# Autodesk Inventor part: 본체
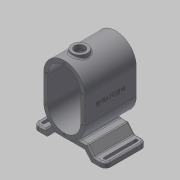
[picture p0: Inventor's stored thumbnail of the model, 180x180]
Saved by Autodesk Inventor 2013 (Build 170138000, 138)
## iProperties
Created: 2016-12
Part Number: 본체
Material: 알루미늄 6061
Document SubType Name: Modeling
Designer: mduedu
Density: 2.71 g/cm^3
Mass: 1017.21 g
Surface Area: 965.782 cm^2
Volume: 375.354 cm^3
Author: mduedu
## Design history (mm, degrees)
sketch "스케치1"
  geometry: L1 (40, -25)-(40, 25); L2 (-40, 25)-(-40, -25); L3 (-40, -25)-(40, 25); L4 (40, -25)-(-40, 25); L5 (0, 25)-(0, -25); A1 r 40 centre (0, 25) between (40, 25) and (-40, 25); A2 r 40 centre (0, -25) between (-40, -25) and (40, -25); 1 further point
  constraints: 10 end point, 4 point on circle, 3 tangent, 2 centre point, 2 midpoint, 2 parallel, 1 vertical
  dimensions: "d0" = 130 dimension on A2 A1; "d2" = 80 distance between parallel lines of L1 L2
extrude "돌출1" new body sketch "스케치1" stored distance "d3" = 100; taper "d4" = 0 deg
feature "쉘1" dims "d5" = 8
sketch "스케치15"
  geometry: L1 (-35, -64.5)-(35, -64.5); L2 (-35, -64.5)-(-47.586, -79.5); L3 (-47.586, -79.5)-(-70, -79.5); L4 (0, -64.5)-(0, 0); L5 (35, -64.5)-(47.586, -79.5); L6 (47.586, -79.5)-(70, -79.5); L7 (70, -89.5)-(42.923, -89.5); L8 (42.923, -89.5)-(30.337, -74.5); L9 (30.337, -74.5)-(-30.337, -74.5); L10 (-30.337, -74.5)-(-42.923, -89.5); L11 (-42.923, -89.5)-(-70, -89.5); L12 (-70, -79.5)-(-70, -89.5); L13 (70, -79.5)-(70, -89.5); A1 r 40 centre (0, -25) between (-40, -25) and (40, -25) reference; 1 further point
  constraints: 26 end point, 2 parallel, 2 perpendicular, 2 symmetric about line, 1 coincident, 1 horizontal, 1 midpoint, 1 vertical, 4 other
  dimensions: "d83" = 10 distance between parallel lines of L9 L1; "d85" = 140 distance between parallel lines of L13 L12; "d86" = 70 distance of L1.start L1.end; "d87" = 25 distance between parallel lines of L11 L1; "d88" = 130 deg angle of L1 L2; "d106" = 0.5 distance edge to line of A1 L1
extrude "돌출6" new body sketch "스케치15" stored distance "d89" = 80; taper "d90" = 0 deg
fillet "모깎기13" dims "d101" = 3
fillet "모깎기15" dims "d103" = 3
fillet "모깎기16" dims "d104" = 10
fillet "모깎기17" dims "d105" = 3
feature "결합2"
  node "솔리드2"
fillet "모깎기18" dims "d107" = 3
sketch "스케치16"
  geometry: L1 (8.015, 67)-(8.015, 7); L2 (14.015, 67)-(14.015, 7); A1 r 10 centre (11.015, 67) between (21.015, 67) and (11.015, 77) reference; A2 r 10 centre (11.015, 7) between (11.015, -3) and (21.015, 7) reference; A3 r 3 centre (11.015, 67) between (8.015, 67) and (14.015, 67); A4 r 3 centre (11.015, 7) between (8.015, 7) and (14.015, 7); 1 further point
  constraints: 4 end point, 4 point on circle, 4 tangent, 2 centre point, 2 coincident
  dimensions: "d108" = 6 diameter of A3; "d109" = 6 diameter of A4
extrude "돌출7" cut sketch "스케치16" stored distance "d110" = 80; taper "d111" = 0 deg
node "작업 평면1"
sketch "스케치9"
  geometry: 1 further point
sketch "스케치7"
  geometry: L1 (40, 50)-(-40, 50) reference; C1 r 15 at (0, 20); 1 further point
  constraints: 1 centre point, 1 vertical alignment
  dimensions: "d40" = 30 diameter of C1; "d41" = 30 distance from line of C1.centre L1
extrude "돌출4" join sketch "스케치7" stored distance "d42" = 80; taper "d43" = 0 deg
hole "구멍2" diameter "d46" = 20; stored, may be unused: countersink angle "d50" = 90 deg, drill point angle "d52" = 118 deg; dims "d44" = 10, "d45" = 10, "d47" = 6, "d48" = 4, "d49" = 2, "d51" = 8
fillet "모깎기4" dims "d53" = 3
node "작업 평면2"
sketch "스케치8"
  geometry: C1 r 15 at (0, 0) reference; C2 r 15 at (0, 0); 1 further point
  constraints: 1 centre point, 1 coincident
  dimensions: "d55" = 30 diameter of C2
extrude "돌출5" cut sketch "스케치8" stored distance "d56" = 80; taper "d57" = 0 deg
chamfer "모따기1" distance "d58" = 1; stored, may be unused: second distance "d59" = 2, angle "d60" = 45 deg
sketch "스케치10"
  geometry: 2 further points
  constraints: 1 coincident, 1 other
feature "엠보싱1" sketch "스케치10" dims "d0" = 130, "d2" = 80, "d61" = 0.5, "d62" = 0
sketch "스케치11"
  geometry: 1 further point
  constraints: 1 other
hole "구멍3" sketch "스케치11" at (0, 60) diameter "d63" = 3.242; stored, may be unused: countersink angle "d67" = 90 deg, drill point angle "d69" = 120 deg; dims "d64" = 8.6, "d65" = 4, "d66" = 2, "d68" = 10.6
sketch "스케치12"
  geometry: 1 further point
  constraints: 1 other
hole "구멍5" sketch "스케치12" at (0, 60) diameter "d70" = 3.242; stored, may be unused: countersink angle "d74" = 90 deg, drill point angle "d76" = 120 deg; dims "d71" = 8.6, "d72" = 4, "d73" = 2, "d75" = 10.6
node "솔리드1"
mirror "대칭2"
pattern_linear "직사각형 패턴1"
pattern_linear "직사각형 패턴2"
sketch "스케치13"
  geometry: L1 (-40, 25)-(-40, -25) reference; L2 (40, -25)-(40, 25) reference; L3 (35, 25)-(35, -25); L4 (-35, -25)-(-35, 25); A1 r 40 centre (0, 25) between (40, 25) and (-40, 25) reference; A2 r 40 centre (0, -25) between (-40, -25) and (40, -25) reference; A3 r 35 centre (0, 25) between (35, 25) and (-35, 25); A4 r 35 centre (0, -25) between (-35, -25) and (35, -25); 2 further points
  constraints: 5 point on circle, 4 end point, 2 centre point, 3 other
  dimensions: "d77" = 5 distance between parallel lines of L3 L2
sketch "스케치14"
  geometry: L1 (-40, 25)-(-40, -25) reference; L2 (40, -25)-(40, 25) reference; L3 (35, 25)-(35, -25); L4 (-35, -25)-(-35, 25); A1 r 40 centre (0, 25) between (40, 25) and (-40, 25) reference; A2 r 40 centre (0, -25) between (-40, -25) and (40, -25) reference; A3 r 35 centre (0, 25) between (35, 25) and (-35, 25); A4 r 35 centre (0, -25) between (-35, -25) and (35, -25); 2 further points
  constraints: 5 point on circle, 4 end point, 2 centre point, 3 other
  dimensions: "d80" = 5 distance between parallel lines of L2 L3
other parameters: "d54" = -8
